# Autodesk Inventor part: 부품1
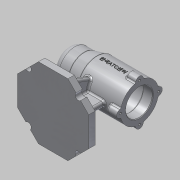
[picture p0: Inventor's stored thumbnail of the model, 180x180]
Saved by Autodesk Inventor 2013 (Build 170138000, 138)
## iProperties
Created: 2019-12
Part Number: 부품1
Material: 알루미늄 6061
Document SubType Name: Modeling
Designer: Administrator
Density: 2.71 g/cm^3
Mass: 728.649 g
Surface Area: 713.108 cm^2
Volume: 268.874 cm^3
Author: Administrator
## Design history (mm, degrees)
sketch "스케치5"
  geometry: L1 (0, 0)-(42.956, 0); L2 (0, 25)-(25, 25); L3 (25, 25)-(45, 30); L4 (45, 30)-(112, 30); L5 (112, 30)-(112, 21); L6 (112, 21)-(97, 21); L7 (97, 21)-(97, 24); L8 (97, 24)-(43, 24); L9 (43, 24)-(43, 21); L10 (43, 21)-(31, 21); L11 (31, 21)-(31, 17.5); L12 (31, 17.5)-(13, 17.5); L13 (13, 17.5)-(13, 16); L14 (13, 16)-(9, 16); L15 (9, 16)-(9, 10.5); L16 (0, 25)-(0, 0); L17 (9, 10.5)-(6, 10.5); L18 (6, 10.5)-(6, 0); L19 (0, 0)-(6, 0)
  constraints: 38 end point, 10 parallel, 5 perpendicular, 2 horizontal, 1 collinear, 1 point on line
  dimensions: "d28" = 50 diameter of L2 L1; "d30" = 112 distance between parallel lines of L5 L16; "d31" = 25 distance from line of L2.end L16; "d32" = 45 distance from line of L3.end L16; "d33" = 60 diameter of L4 L1; "d34" = 15 distance between parallel lines of L5 L7; "d35" = 42 diameter of L6 L1; "d36" = 54 distance between parallel lines of L7 L9; "d37" = 48 diameter of L8 L1; "d39" = 42 diameter of L10 L1; "d40" = 12 distance between parallel lines of L9 L11; "d41" = 18 distance between parallel lines of L13 L11; "d42" = 35 diameter of L12 L1; "d43" = 4 distance between parallel lines of L13 L15; "d44" = 32 diameter of L14 L1; "d45" = 3 distance between parallel lines of L15 L18; "d46" = 21 diameter of L17 L1
revolve "회전1" sketch "스케치5" stored, may be unused: angle "d47" = 90 deg
node "작업 평면1"
sketch "스케치6"
  geometry: L1 (-79.196, -56)-(-112, -23.196); L2 (-112, -23.196)-(-112, 23.196); L3 (-112, 23.196)-(-79.196, 56); L4 (-79.196, 56)-(-32.804, 56); L5 (-32.804, 56)-(0, 23.196); L6 (0, 23.196)-(0, -23.196); L7 (0, -23.196)-(-32.804, -56); L8 (-32.804, -56)-(-79.196, -56); L9 (-56, 0)-(-16.402, -39.598); L10 (0, 0)-(-56, 0); L11 (-56, 0)-(-16.402, 39.598); C1 r 56 at (-56, 0); 2 further points
  constraints: 22 end point, 4 midpoint, 2 horizontal alignment, 1 centre point, 1 coincident, 1 parallel, 1 perpendicular, 1 tangent, 1 vertical, 17 other
  dimensions: "d49" = 112 diameter of C1; "d51" = 45 deg angle of L10 L9
extrude "돌출1" join sketch "스케치6" distance "d53" = 10; taper "d54" = 0 deg
sketch "스케치7"
  geometry: L1 (79.196, 56)-(32.804, 56) reference; L2 (32.804, -56)-(79.196, -56) reference; L3 (112, -23.196)-(112, 23.196) reference; L4 (0, 23.196)-(32.804, 56) reference; L5 (0, 0)-(112, 0); L6 (56, 56)-(56, -56); L7 (56, 0)-(16.402, 39.598); C1 r 5 at (16.402, 39.598); C2 r 5 at (16.402, -39.598); C3 r 5 at (95.598, -39.598); C4 r 5 at (95.598, 39.598)
  constraints: 6 end point, 5 midpoint, 4 centre point, 1 perpendicular, 9 other
  dimensions: "d55" = 10 diameter of C1; "d61" = 360 deg dimension on L7.start L7.end (derived)
extrude "돌출2" cut sketch "스케치7" distance "d57" = 10; taper "d58" = 0 deg
sketch "스케치8"
  geometry: L1 (112, -23.196)-(112, 23.196) reference; L2 (0, 23.196)-(0, -23.196) reference; L3 (52, 4)-(87, 4); L4 (87, 4)-(87, -4); L5 (87, -4)-(52, -4); L6 (52, -4)-(52, 4); 3 further points
  constraints: 8 end point, 2 midpoint, 2 parallel, 1 horizontal, 1 horizontal alignment, 1 perpendicular
  dimensions: "d63" = 8 distance between parallel lines of L3 L5; "d65" = 25 distance between parallel lines of L1 L4; "d66" = 60 distance between parallel lines of L1 L6
extrude "돌출3" join sketch "스케치8" stored distance "d67" = 10; taper "d68" = 0 deg
node "작업 평면2"
sketch "스케치9"
  geometry: L1 (-10, -59.196)-(-56.766, -42.174); L2 (0, -79.196)-(-10, -79.196) reference; L3 (-10, -66.329)-(-10, -79.196) reference; 2 further points
  constraints: 2 end point, 1 point on line, 2 other
  dimensions: "d70" = 110 deg angle of L1 L3; "d71" = 20 distance from line of L1.start L2
feature "리브1" sketch "스케치9" dims "d72" = 1, "d73" = 8, "d74" = 0, "d75" = 0, "d76" = 1, "d77" = 1
node "작업 평면3"
sketch "스케치10"
  geometry: L1 (54.196, 55)-(34.196, 50) reference; L2 (41.672, 51.869)-(61.196, 10); L3 (57.794, 10)-(66.329, 10) reference; L4 (79.196, 0)-(79.196, 10) reference; L5 (79.196, 10)-(66.329, 10) reference; 2 further points
  constraints: 2 end point, 2 point on line
  dimensions: "d78" = 18 distance from line of L4 L2.end; "d79" = 115 deg angle of L5 L2
feature "리브2" sketch "스케치10" dims "d80" = 1, "d81" = 8, "d82" = 0, "d83" = 0, "d84" = 1, "d85" = 1
sketch "스케치11"
  geometry: C1 r 6 at (0, 30); C2 r 6 at (-30, 0); C3 r 6 at (0, -30); C4 r 6 at (30, 0); 1 further point
  constraints: 4 centre point, 2 vertical alignment, 10 other
  dimensions: "d86" = 12 diameter of C1; "d91" = 360 deg dimension on point (0, 0) C1.centre (derived)
extrude "돌출4" join sketch "스케치11" distance "d93" = 16; taper "d94" = 0 deg
sketch "스케치12"
  geometry: A1 r 6 centre (30, 30) between (35.97, 29.4) and (24.03, 29.4) reference; A2 r 6 centre (0, 0) between (0.6, 5.97) and (0.6, -5.97) reference; A3 r 6 centre (30, -30) between (24.03, -29.4) and (35.97, -29.4) reference; A4 r 6 centre (60, 0) between (59.4, -5.97) and (59.4, 5.97) reference
hole "구멍1" sketch "스케치12" at (30, 30), (0, 0), (30, -30), (60, 0) diameter "d95" = 3.242; stored, may be unused: countersink angle "d99" = 90 deg, drill point angle "d101" = 118 deg; dims "d96" = 8, "d97" = 4, "d98" = 2, "d100" = 11
fillet "모깎기1" dims "d102" = 3, "d103" = 0.3
chamfer "모따기1" distance "d104" = 1; stored, may be unused: second distance "d105" = 2, angle "d106" = 45 deg
fillet "모깎기2" dims "d107" = 3, "d108" = 10, "d109" = 1
fillet "모깎기3" dims "d110" = 3
node "작업 평면5"
  node "작업 평면4"
sketch "스케치13"
  geometry: L1 (33.5, 8.017)-(33.5, 28.909) reference; 2 further points
  constraints: 1 horizontal alignment, 1 other
  dimensions: "d112" = 41 distance from line of L1 point (-7.5, 0)
feature "엠보싱1" sketch "스케치13" dims "d28" = 50, "d30" = 112, "d31" = 25, "d32" = 45, "d33" = 60, "d34" = 15, "d35" = 42, "d36" = 54, "d37" = 48, "d39" = 42, "d40" = 12, "d41" = 18, "d42" = 35, "d43" = 4, "d44" = 32, "d45" = 3, "d46" = 21, "d48" = -80, "d113" = 0.5, "d114" = 0
node "솔리드1"
mirror "대칭1"
